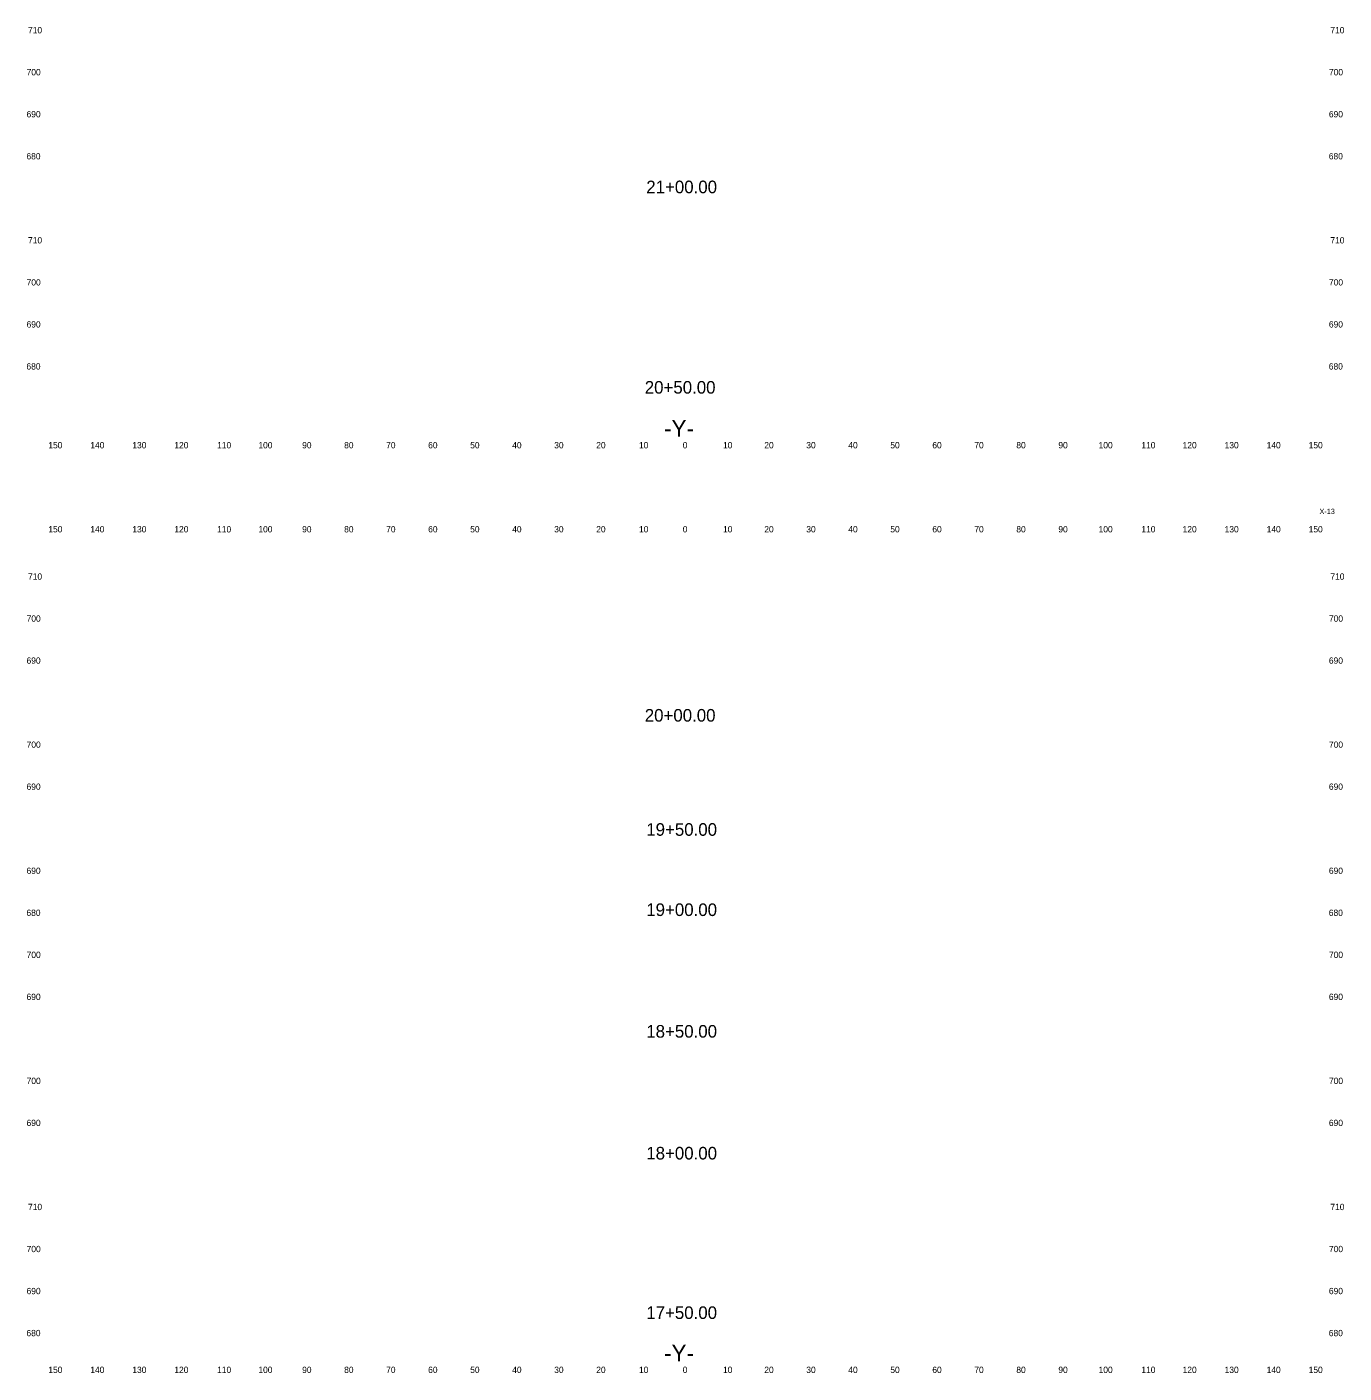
# Model space of a CAD drawing. Extents: x 3 to 317, y 1 to 1307.
# Drawn here: x 3.3 to 316.9, y 1.2 to 321.5 of the extents above; entities that cross this region are included whole.
import ezdxf

# ---------------------------------------------------------------- set-up
doc = ezdxf.new("R2010")
doc.units = 0
for name, color, linetype in [('Prop XS Alignment Label', 7, 'Continuous'), ('Prop XS Elevation Labels', 7, 'Continuous'), ('Prop XS Offset Labels', 7, 'Continuous'), ('Prop XS Sheet Number', 7, 'Continuous'), ('Prop XS Station Labels', 7, 'Continuous')]:
    doc.layers.add(name, color=color, linetype=linetype)

msp = doc.modelspace()

# ---------------------------------------------------------------- texts
at = {"layer": 'Prop XS Alignment Label'}
for p in [(155, 224), (155, 4)]:
    msp.add_text('-Y-', height=4, dxfattribs=at).set_placement(p)
at = {"layer": 'Prop XS Elevation Labels'}
for s, p in [('710', (3.61, 320)), ('710', (313.61, 320)), ('700', (3.28, 310)), ('700', (313.28, 310)), ('690', (3.26, 300)), ('690', (313.26, 300)), ('680', (3.24, 290)), ('680', (313.24, 290)), ('710', (3.61, 270)), ('710', (313.61, 270)), ('700', (3.28, 260)), ('700', (313.28, 260)), ('690', (3.26, 250)), ('690', (313.26, 250)), ('680', (3.24, 240)), ('680', (313.24, 240)), ('710', (3.61, 190)), ('710', (313.61, 190)), ('700', (3.28, 180)), ('700', (313.28, 180)), ('690', (3.26, 170)), ('690', (313.26, 170)), ('700', (3.28, 150)), ('700', (313.28, 150)), ('690', (3.26, 140)), ('690', (313.26, 140)), ('690', (3.26, 120)), ('690', (313.26, 120)), ('680', (3.24, 110)), ('680', (313.24, 110)), ('700', (3.28, 100)), ('700', (313.28, 100)), ('690', (3.26, 90)), ('690', (313.26, 90)), ('700', (3.28, 70)), ('700', (313.28, 70)), ('690', (3.26, 60)), ('690', (313.26, 60)), ('710', (3.61, 40)), ('710', (313.61, 40)), ('700', (3.28, 30)), ('700', (313.28, 30)), ('690', (3.26, 20)), ('690', (313.26, 20)), ('680', (3.24, 10)), ('680', (313.24, 10))]:
    msp.add_text(s, height=1.5, dxfattribs=at).set_placement(p)
at = {"layer": 'Prop XS Offset Labels'}
for s, p in [('150', (8.44, 221.25)), ('140', (18.44, 221.25)), ('130', (28.44, 221.25)), ('120', (38.44, 221.25)), ('110', (48.62, 221.25)), ('100', (58.44, 221.25)), ('90', (68.86, 221.25)), ('80', (78.86, 221.25)), ('70', (88.86, 221.25)), ('60', (98.86, 221.25)), ('50', (108.86, 221.25)), ('40', (118.86, 221.25)), ('30', (128.86, 221.25)), ('20', (138.86, 221.25)), ('10', (149.04, 221.25)), ('0', (159.45, 221.25)), ('10', (169.04, 221.25)), ('20', (178.86, 221.25)), ('30', (188.86, 221.25)), ('40', (198.86, 221.25)), ('50', (208.86, 221.25)), ('60', (218.86, 221.25)), ('70', (228.86, 221.25)), ('80', (238.86, 221.25)), ('90', (248.86, 221.25)), ('100', (258.44, 221.25)), ('110', (268.62, 221.25)), ('120', (278.44, 221.25)), ('130', (288.44, 221.25)), ('140', (298.44, 221.25)), ('150', (308.44, 221.25)), ('150', (8.44, 201.25)), ('140', (18.44, 201.25)), ('130', (28.44, 201.25)), ('120', (38.44, 201.25)), ('110', (48.62, 201.25)), ('100', (58.44, 201.25)), ('90', (68.86, 201.25)), ('80', (78.86, 201.25)), ('70', (88.86, 201.25)), ('60', (98.86, 201.25)), ('50', (108.86, 201.25)), ('40', (118.86, 201.25)), ('30', (128.86, 201.25)), ('20', (138.86, 201.25)), ('10', (149.04, 201.25)), ('0', (159.45, 201.25)), ('10', (169.04, 201.25)), ('20', (178.86, 201.25)), ('30', (188.86, 201.25)), ('40', (198.86, 201.25)), ('50', (208.86, 201.25)), ('60', (218.86, 201.25)), ('70', (228.86, 201.25)), ('80', (238.86, 201.25)), ('90', (248.86, 201.25)), ('100', (258.44, 201.25)), ('110', (268.62, 201.25)), ('120', (278.44, 201.25)), ('130', (288.44, 201.25)), ('140', (298.44, 201.25)), ('150', (308.44, 201.25)), ('150', (8.44, 1.25)), ('140', (18.44, 1.25)), ('130', (28.44, 1.25)), ('120', (38.44, 1.25)), ('110', (48.62, 1.25)), ('100', (58.44, 1.25)), ('90', (68.86, 1.25)), ('80', (78.86, 1.25)), ('70', (88.86, 1.25)), ('60', (98.86, 1.25)), ('50', (108.86, 1.25)), ('40', (118.86, 1.25)), ('30', (128.86, 1.25)), ('20', (138.86, 1.25)), ('10', (149.04, 1.25)), ('0', (159.45, 1.25)), ('10', (169.04, 1.25)), ('20', (178.86, 1.25)), ('30', (188.86, 1.25)), ('40', (198.86, 1.25)), ('50', (208.86, 1.25)), ('60', (218.86, 1.25)), ('70', (228.86, 1.25)), ('80', (238.86, 1.25)), ('90', (248.86, 1.25)), ('100', (258.44, 1.25)), ('110', (268.62, 1.25)), ('120', (278.44, 1.25)), ('130', (288.44, 1.25)), ('140', (298.44, 1.25)), ('150', (308.44, 1.25))]:
    msp.add_text(s, height=1.5, dxfattribs=at).set_placement(p)
at = {"layer": 'Prop XS Sheet Number'}
msp.add_text('X-13', height=1.25, dxfattribs=at).set_placement((311.03, 205.63))
at = {"layer": 'Prop XS Station Labels'}
for s, p in [('21+00.00', (150.77, 281.95)), ('20+50.00', (150.41, 234.27)), ('20+00.00', (150.41, 156.23)), ('19+50.00', (150.77, 129.07)), ('19+00.00', (150.77, 109.98)), ('18+50.00', (150.77, 81.04)), ('18+00.00', (150.77, 52.05)), ('17+50.00', (150.77, 14.1))]:
    msp.add_text(s, height=3, dxfattribs=at).set_placement(p)

doc.saveas('drawing.dxf')
